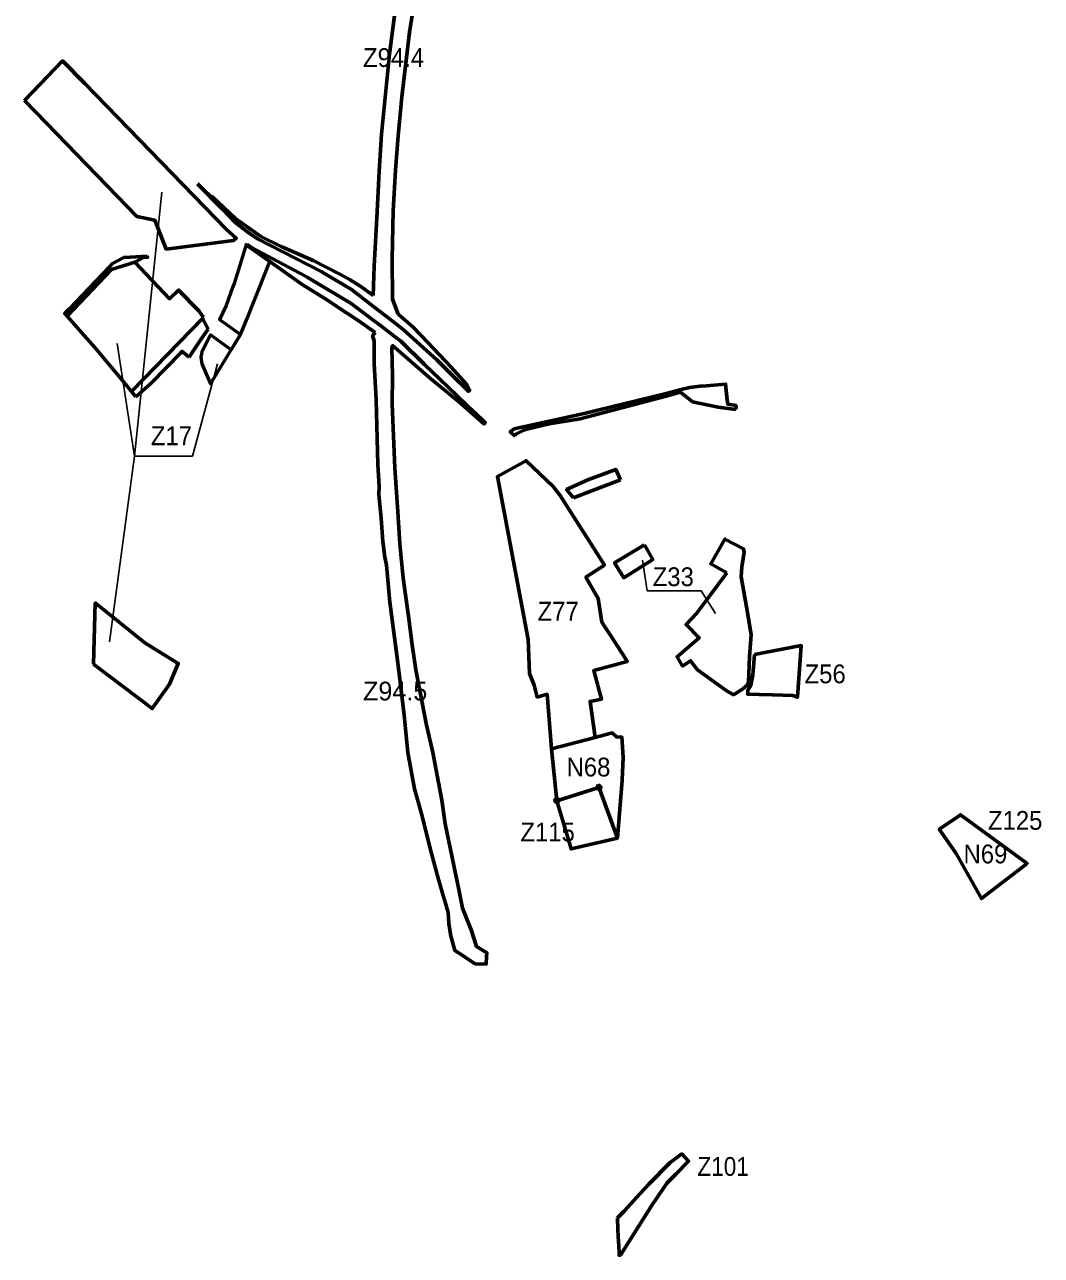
# Model space of a CAD drawing. Extents: x -650277 to -643422, y -1073980 to -1066720.
# Drawn here: x -645817 to -644519, y -1073665 to -1072093 of the extents above; entities that cross this region are included whole.
import ezdxf

# ---------------------------------------------------------------- set-up
doc = ezdxf.new("R2010")
doc.units = 0
doc.header["$LTSCALE"] = 9.6
doc.header["$PDMODE"] = 32
doc.header["$PDSIZE"] = 4.8
for name, color, linetype, lineweight in [('1', 7, 'Continuous', 60), ('15', 7, 'Continuous', 60), ('3', 7, 'Continuous', 60), ('42', 7, 'Continuous', 60), ('60', 7, 'Continuous', 60), ('63', 7, 'Continuous', 25), ('9', 7, 'Continuous', 60)]:
    doc.layers.add(name, color=color, linetype=linetype, lineweight=lineweight)

msp = doc.modelspace()

# ---------------------------------------------------------------- linework, layer by layer
at = {"layer": '1'}
for points in [[(-645817.219, -1072189.975), (-645768.649, -1072139.283), (-645740.45, -1072168.23), (-645559.34, -1072354.42), (-645546.82, -1072365.72), (-645550.41, -1072368.47), (-645636.37, -1072379.57), (-645650.78, -1072342.73), (-645674, -1072338), (-645789.298, -1072218.833)], [(-645588.78, -1072467), (-645594.83, -1072458.48), (-645620.56, -1072432), (-645632.1, -1072442.93), (-645676.53, -1072396.16), (-645706.039, -1072405.769), (-645763.06, -1072465.26), (-645753.128, -1072476.383), (-645744.38, -1072486.18), (-645726.95, -1072505.7), (-645709.92, -1072526.3), (-645694.51, -1072544.93), (-645680.87, -1072561.42)], [(-645729.36, -1072909.65), (-645654.16, -1072966.3), (-645632.23, -1072935.28), (-645620.92, -1072908.65), (-645663.52, -1072882.58), (-645726.9, -1072831.5)], [(-644536.62, -1073164.33), (-644536.62, -1073164.33), (-644622.03, -1073101.88), (-644622.03, -1073101.88), (-644630.58, -1073107.78), (-644648.95, -1073120.47), (-644627.53, -1073151.26), (-644604.13, -1073193), (-644595.18, -1073208.98)]]:
    msp.add_lwpolyline(points, close=True, dxfattribs=at)
at = {"layer": '1', "lineweight": 53}
msp.add_lwpolyline([(-645503.98, -1072395.64), (-645532.75, -1072375.41), (-645535.05, -1072376.72), (-645549.6, -1072423.39), (-645551.54, -1072428.66), (-645559.92, -1072451.41), (-645568.38, -1072469.68), (-645541.56, -1072488.74), (-645553.35, -1072508.1), (-645579.92, -1072489.22), (-645581.13, -1072491), (-645591.06, -1072511.06), (-645592.08, -1072517.43), (-645591.03, -1072526.14), (-645579.76, -1072551.45), (-645541.09, -1072487.98), (-645533.15, -1072468.21), (-645524.87, -1072447.61)], close=True, dxfattribs=at)
at = {"layer": '1', "lineweight": 25}
msp.add_lwpolyline([(-645571, -1072526), (-645603, -1072644), (-645677, -1072644)], dxfattribs=at)
at = {"layer": '15'}
for points in [[(-645661.3, -1072388.74), (-645682.59, -1072389.76), (-645690.37, -1072390.13), (-645705, -1072398.19), (-645708.94, -1072402.11)], [(-645676.53, -1072396.16), (-645676.53, -1072396.16), (-645665.32, -1072390.32), (-645660.16, -1072389.95), (-645661.3, -1072388.74)], [(-645708.94, -1072402.11), (-645760.02, -1072455.94), (-645765.95, -1072462.03), (-645763.06, -1072465.26)], [(-645763.06, -1072465.26), (-645706.039, -1072405.769), (-645676.53, -1072396.16)], [(-645582.84, -1072481.71), (-645584.46, -1072478.58), (-645589.862, -1072468.109), (-645680.87, -1072561.42), (-645675.13, -1072568.36)], [(-645607.07, -1072517.61), (-645605.95, -1072515.95), (-645604.82, -1072514.3), (-645592.9, -1072496.52), (-645583.13, -1072482.13), (-645582.84, -1072481.71)], [(-645675.13, -1072568.36), (-645655.65, -1072550.62), (-645617.87, -1072512.12), (-645615.95, -1072510.16), (-645607.07, -1072517.61)], [(-644919.75, -1072572.43), (-644921.84, -1072552.03), (-644926.81, -1072552.51)], [(-644926.81, -1072552.51), (-644946.57, -1072554.22), (-644954.57, -1072554.43), (-644967.97, -1072556.17), (-644978.56, -1072558.74), (-644999.72, -1072564.24), (-645102.73, -1072589.74), (-645192.06, -1072609.19), (-645197.044, -1072612.821), (-645190.71, -1072618.6)], [(-645147.13, -1072602.79), (-645107.58, -1072596.47), (-644997.92, -1072567.23), (-644979.55, -1072562.44), (-644963.97, -1072574.57)], [(-644963.97, -1072574.57), (-644931.48, -1072581.26), (-644909.02, -1072584.28)], [(-644909.02, -1072584.28), (-644908.59, -1072579.51), (-644919.23, -1072577.46), (-644919.75, -1072572.43)], [(-645190.71, -1072618.6), (-645190.59, -1072616.28), (-645179.6, -1072610.94), (-645177.56, -1072609.89), (-645147.13, -1072602.79)], [(-645056.08, -1072674.07), (-645062.131, -1072660.856), (-645098.016, -1072674.425), (-645115.56, -1072682.406), (-645124.933, -1072686.721), (-645116.11, -1072697.15)], [(-645116.11, -1072697.15), (-645100.9, -1072691.31), (-645056.08, -1072674.07)]]:
    msp.add_lwpolyline(points, dxfattribs=at)
at = {"layer": '3'}
for points in [[(-644902.18, -1072797.88), (-644901.35, -1072785.36), (-644898.29, -1072766.55), (-644899.2, -1072762.14), (-644922.88, -1072749.97), (-644940.8, -1072781.48), (-644920.46, -1072792.92)], [(-644920.46, -1072792.92), (-644945.2, -1072826.3), (-644959.24, -1072844.92), (-644972.28, -1072859.02), (-644955.49, -1072875.78), (-644983.93, -1072900.24), (-644977.16, -1072912.11), (-644966.57, -1072905.23), (-644957.79, -1072916.73), (-644921.18, -1072943.17), (-644911.87, -1072948.76), (-644900.2, -1072941.67), (-644893.77, -1072935.88), (-644892.86, -1072932.6), (-644891.2, -1072900.09), (-644889.11, -1072871.66), (-644895.32, -1072836.6), (-644902.18, -1072797.88)], [(-645137.5, -1073083.97), (-645119.34, -1073145.61), (-645060.1, -1073131.68), (-645082.6, -1073069.93), (-645083.681, -1073066.962)]]:
    msp.add_lwpolyline(points, dxfattribs=at)
for points in [[(-645025.61, -1072757.17), (-645063.6, -1072780.26), (-645051.94, -1072799.21), (-645015.02, -1072776.01)], [(-645054.12, -1073057.62), (-645052.94, -1073028.58), (-645054.44, -1073002.54), (-645060.95, -1073002.68), (-645066.66, -1072997.3), (-645074.333, -1072999.365), (-645088.62, -1073003.45), (-645144.37, -1073017.64), (-645137.5, -1073083.97), (-645083.681, -1073066.962), (-645082.6, -1073069.93), (-645060.1, -1073131.68)]]:
    msp.add_lwpolyline(points, close=True, dxfattribs=at)
for p in [(-645083.681, -1073066.962), (-645137.5, -1073083.97)]:
    msp.add_point(p, dxfattribs=at)
at = {"layer": '42'}
msp.add_lwpolyline([(-645817.219, -1072189.975), (-645768.649, -1072139.283), (-645740.45, -1072168.23), (-645559.34, -1072354.42), (-645546.82, -1072365.72), (-645550.41, -1072368.47), (-645636.37, -1072379.57), (-645650.78, -1072342.73), (-645674, -1072338), (-645789.298, -1072218.833)], close=True, dxfattribs=at)
at = {"layer": '60'}
for points in [[(-645339.904, -1072462.677), (-645347.551, -1072443.527), (-645347.677, -1072391.355), (-645346.62, -1072330.914), (-645343.458, -1072278.998), (-645339.908, -1072235.158), (-645335.367, -1072185.207), (-645325.498, -1072102.789), (-645309.01, -1071998.147), (-645285.617, -1071875.733), (-645244.798, -1071696.585), (-645235.793, -1071663.703), (-645230.436, -1071634.261), (-645227.905, -1071625.277), (-645222.48, -1071606.08)], [(-645313.153, -1071883.081), (-645326.343, -1071952.807), (-645334.118, -1072001.954), (-645339.455, -1072031.565), (-645344.819, -1072081.225), (-645351.358, -1072130.815), (-645361.317, -1072232.824), (-645364.435, -1072280.268), (-645366.951, -1072331.609), (-645370.624, -1072401.447), (-645372.228, -1072438.764)], [(-645372.228, -1072438.764), (-645387.894, -1072427.453), (-645401.441, -1072419.033), (-645414.631, -1072411.611), (-645448.831, -1072394.325), (-645488.64, -1072376.782), (-645515.437, -1072363.447), (-645547.593, -1072340.827), (-645577.33, -1072312.704), (-645579.217, -1072312.425), (-645596.405, -1072296.114)], [(-645596.405, -1072296.114), (-645564.4, -1072328.61), (-645547.72, -1072346.19), (-645532.07, -1072358.01), (-645531.65, -1072358.29), (-645528.27, -1072360.53), (-645519.57, -1072366.3), (-645438.64, -1072408.1)], [(-645533.08, -1072373.71), (-645534.3, -1072374.33), (-645532.75, -1072375.41), (-645503.98, -1072395.64)], [(-645370.226, -1072471.736), (-645396.94, -1072451.44), (-645400.12, -1072449.03), (-645456.52, -1072415.6), (-645459.31, -1072413.95), (-645465.793, -1072410.498), (-645527.33, -1072377.73), (-645533.08, -1072373.71)], [(-645503.98, -1072395.64), (-645462.65, -1072425.01), (-645462.651, -1072425.011), (-645462.646, -1072425.015)], [(-645438.64, -1072408.1), (-645437.6, -1072408.64), (-645434.19, -1072410.67), (-645399.77, -1072431.12), (-645371.356, -1072453.119), (-645342.284, -1072475.625)], [(-645462.646, -1072425.015), (-645433.91, -1072442.56), (-645404.64, -1072461.72), (-645389.731, -1072471.612), (-645369.364, -1072485.931)], [(-645345.079, -1072490.836), (-645362.81, -1072477.37), (-645370.226, -1072471.736)], [(-645290.76, -1072520.92), (-645271.74, -1072539.96), (-645249.9, -1072561.25), (-645248.967, -1072559.511), (-645252.768, -1072552.178), (-645265.009, -1072538.358), (-645272.276, -1072530.154), (-645302.303, -1072499.014), (-645320.805, -1072479.495), (-645339.904, -1072462.677)], [(-645369.364, -1072485.931), (-645372.72, -1072490.314), (-645370.928, -1072496.619), (-645370.755, -1072525.734), (-645368.173, -1072571.881), (-645366.022, -1072654.462), (-645364.524, -1072682.575), (-645364.786, -1072692.977), (-645362.708, -1072714.781)], [(-645342.284, -1072475.625), (-645333.62, -1072482.33), (-645290.76, -1072520.92)], [(-645338.023, -1072755.969), (-645339.96, -1072721.587), (-645344.152, -1072658.857), (-645347.795, -1072577.893), (-645347.214, -1072540.97), (-645348.253, -1072505.583), (-645347.292, -1072502.877), (-645298.498, -1072545.352)], [(-645242, -1072588.6), (-645263.7, -1072567.8), (-645276.93, -1072555.11), (-645306.46, -1072527.08), (-645336.33, -1072497.48), (-645336.887, -1072497.057), (-645345.079, -1072490.836)], [(-645298.498, -1072545.352), (-645263.217, -1072574.314), (-645230.845, -1072602.888), (-645228.96, -1072600.865), (-645241.87, -1072588.722), (-645242, -1072588.6)], [(-645362.708, -1072714.781), (-645361.874, -1072723.527), (-645359.76, -1072752.865), (-645357.272, -1072772.771), (-645355.121, -1072782.993)], [(-645317.65, -1072916.642), (-645322.284, -1072885.085), (-645327.091, -1072848.387), (-645333.718, -1072799.987), (-645338.023, -1072755.969)], [(-645355.121, -1072782.993), (-645354.019, -1072792.454), (-645350.822, -1072830.388), (-645340.345, -1072908.029), (-645337.34, -1072932.073), (-645332.517, -1072974.538), (-645327.554, -1073022.214)], [(-645304.24, -1072985.372), (-645311.772, -1072947.945), (-645317.65, -1072916.642)], [(-645257.842, -1073221.36), (-645262.388, -1073199.409), (-645279.878, -1073113.356), (-645284.269, -1073083.286), (-645295.788, -1073022.556), (-645304.24, -1072985.372)], [(-645327.554, -1073022.214), (-645319.052, -1073068.6), (-645310.558, -1073098.946), (-645297.395, -1073151.294), (-645288.647, -1073184.518), (-645276.125, -1073226.571), (-645275.269, -1073240.71), (-645272.747, -1073256.762), (-645271.518, -1073261.16), (-645267.525, -1073275.443), (-645263.03, -1073278.25), (-645241.72, -1073292.2), (-645227.744, -1073292.736), (-645227.199, -1073283.366), (-645226.847, -1073278.345), (-645239.9, -1073270.025), (-645247.051, -1073248.736), (-645257.842, -1073221.36)]]:
    msp.add_lwpolyline(points, dxfattribs=at)
at = {"layer": '63'}
msp.add_line((-645677, -1072644), (-645642, -1072307), dxfattribs=at)
for points in [[(-645709, -1072881), (-645677, -1072644), (-645699, -1072500)], [(-645027.959, -1072776.842), (-645022, -1072816), (-644953, -1072816), (-644935, -1072845)]]:
    msp.add_lwpolyline(points, dxfattribs=at)
at = {"layer": '9'}
for points in [[(-645144.37, -1073017.64), (-645088.62, -1073003.45), (-645095.04, -1072957.07), (-645080.61, -1072954.43), (-645083.13, -1072944.94), (-645090.34, -1072917.86), (-645047.42, -1072906.05), (-645050.6, -1072901.03), (-645069.55, -1072872.12), (-645071.87, -1072868.45), (-645079.81, -1072855.89), (-645084.47, -1072825.67), (-645100.27, -1072798.46), (-645076.66, -1072783.06), (-645099.58, -1072746.945), (-645121.96, -1072711.68), (-645133.26, -1072694.17), (-645142.1, -1072682.57), (-645176.757, -1072649.968), (-645180.05, -1072651.77), (-645213.34, -1072669.98), (-645174.13, -1072877.93), (-645172.28, -1072921.42), (-645166.48, -1072936.5), (-645162.379, -1072951.55), (-645149.84, -1072948.13)], [(-644884.94, -1072897.19), (-644886.98, -1072923.48), (-644889.65, -1072936.67), (-644893.37, -1072942.61), (-644893.59, -1072947.97), (-644878.86, -1072948.42), (-644861.93, -1072948.94), (-644835.99, -1072949.74), (-644830.25, -1072951.9), (-644825.25, -1072885.96)]]:
    msp.add_lwpolyline(points, close=True, dxfattribs=at)
for points in [[(-645056.06, -1073664.2), (-645043.35, -1073644.04), (-645015.55, -1073599.96), (-645001.267, -1073578.582), (-644996.41, -1073571.97), (-644985.66, -1073560.69), (-644969.117, -1073544.254), (-644977.924, -1073535.072), (-644993.044, -1073546.324), (-645020.11, -1073573.585), (-645035.303, -1073590.199), (-645051.513, -1073608.124), (-645060.009, -1073616.53)], [(-645060.009, -1073616.53), (-645059.35, -1073631.3), (-645058.96, -1073640.09), (-645058.65, -1073647), (-645058.42, -1073652.18), (-645058.01, -1073661.37), (-645057.87, -1073664.55), (-645056.06, -1073664.2)]]:
    msp.add_lwpolyline(points, dxfattribs=at)

# ---------------------------------------------------------------- texts
at = {"layer": '1', "width": 0.95}
for s, p in [('Z17', (-645656, -1072630)), ('Z125', (-644586.786, -1073121.127))]:
    msp.add_text(s, height=24, dxfattribs=at).set_placement(p)
at = {"layer": '63'}
for s, width, p in [('Z94.4', 0.95, (-645385, -1072147)), ('Z33', 0.95, (-645015, -1072810)), ('Z77', 0.95, (-645162, -1072854)), ('Z56', 0.95, (-644821, -1072934)), ('N68', 0.95, (-645125, -1073053)), ('Z115', 0.95, (-645184, -1073136)), ('N69', 0.95, (-644618, -1073164)), ('Z101', 0.9, (-644958, -1073563))]:
    msp.add_text(s, height=24, dxfattribs=dict(at, width=width)).set_placement(p)
msp.add_text('Z94.5', height=24, dxfattribs=at).set_placement((-645385, -1072956))

doc.saveas('drawing.dxf')
